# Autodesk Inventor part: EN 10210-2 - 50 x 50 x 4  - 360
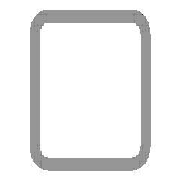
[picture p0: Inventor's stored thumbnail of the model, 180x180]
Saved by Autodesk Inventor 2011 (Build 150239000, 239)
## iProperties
IsCustomPart: 1
Created: 2020-12
Part Number: EN 10210-2 - 50 x 50 x 4  - 360
Material: Steel, Mild
Description: Tube 50*50*4
Document SubType Name: Modeling
Standard: DIN
Designer: PC
Standard Revision: 1997
Standards Organization: DIN
Language: en-US
Size Designation: 50 x 50 x 4
Categories: <MemberInstance><Categories><Category DisplayName="Structural Shapes" InternalName="089c4875-fa83-4c05-b084-43b9cc11f5ed" Mnemonic="GRDR"><CategoryParameter Dis
Stock Number: 50 x 50 x 4
Density: 7.86 g/cm^3
_CCFamilyMember: 15
_CCFamilyDisplayName: DIN EN 10219-2 (Square Hollow Section - Cold Formed) - Cold formed welded structural hollow sections of non-alloy and fine grain structural steel
_FrameMemberDoc: Frame Member File
_Version: 15.0.0
_GetPNFromCC: 1
G_L: 360.000 mm
G_W: 50.000 mm
G_H: 50.000 mm
+F4B11678-982F-45FD-8C75-207517ECF4D8+CUTDETAIL1: Miter 45.00 deg
Author: PC
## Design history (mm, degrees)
node "Start plane"
node "End plane"
sketch "Sketch"
  geometry: L1 (-25, -17)-(-25, 17); L2 (-17, 25)-(17, 25); L3 (25, 17)-(25, -17); L4 (17, -25)-(-17, -25); L5 (-17, 21)-(17, 21); L6 (21, 17)-(21, -17); L7 (17, -21)-(-17, -21); L8 (-21, -17)-(-21, 17); L9 (0, 37.32)-(0, -37.32) reference; L10 (-37.32, 0)-(37.32, 0) reference; A1 r 8 centre (-17, -17) between (-25, -17) and (-17, -25); A2 r 8 centre (-17, 17) between (-17, 25) and (-25, 17); A3 r 8 centre (17, 17) between (25, 17) and (17, 25); A4 r 8 centre (17, -17) between (17, -25) and (25, -17); A5 r 4 centre (-17, 17) between (-17, 21) and (-21, 17); A6 r 4 centre (17, 17) between (21, 17) and (17, 21); A7 r 4 centre (17, -17) between (17, -21) and (21, -17); A8 r 4 centre (-17, -17) between (-21, -17) and (-17, -21)
  constraints: 16 end point, 16 point on circle, 8 centre point, 8 tangent, 4 parallel, 3 equal radius, 2 perpendicular, 7 other
  dimensions: "d7" = 8 radius of A1 (= G_IR); "d10" = 50 distance between parallel lines of L2 L4 (= G_H); "d11" = 50 distance between parallel lines of L1 L3 (= G_W); "d12" = 4 distance between parallel lines of L3 L6 (= G_T); "d15" = 25 distance between parallel lines of L2 L10 (= 0.5 x d10); "d16" = 25 distance between parallel lines of L9 L3 (= 0.5 x d11)
extrude "Body" new body sketch "Sketch" stored distance "d3" = 360 (= G_L); taper "d4" = 0 deg
node "Driven Length"
  sketch "Sketch3"
    geometry: L1 (0, 0)-(10, 0) reference
    constraints: 2 end point, 1 horizontal
  workplane "Work Plane3"
  sketch "Sketch4"
    geometry: L1 (-2, 0)-(12, 0) reference; L2 (-2, 360)-(12, 360) reference
    dimensions: "d18" = 360 distance between parallel lines of L1 L2 (derived)
workplane "Work Plane4"
split "Split1"
body "Solid1"
other parameters: "G_W" = 50 [user parameter; used in 1 equation term], "G_H" = 50 [user parameter; used in 1 equation term], "G_T" = 4 [user parameter; used in 1 equation term], "G_IR" = 8 [user parameter; used in 1 equation term], "G_L" = 360 (= d18) [user parameter; used in 1 equation term], "G_OFFSET_START" = 0 [user parameter; used in 1 equation term], "G_OFFSET_END" = 0 [user parameter; used in 1 equation term], "d13" = 0 (computed from G_OFFSET_START), "d17" = 90 deg
